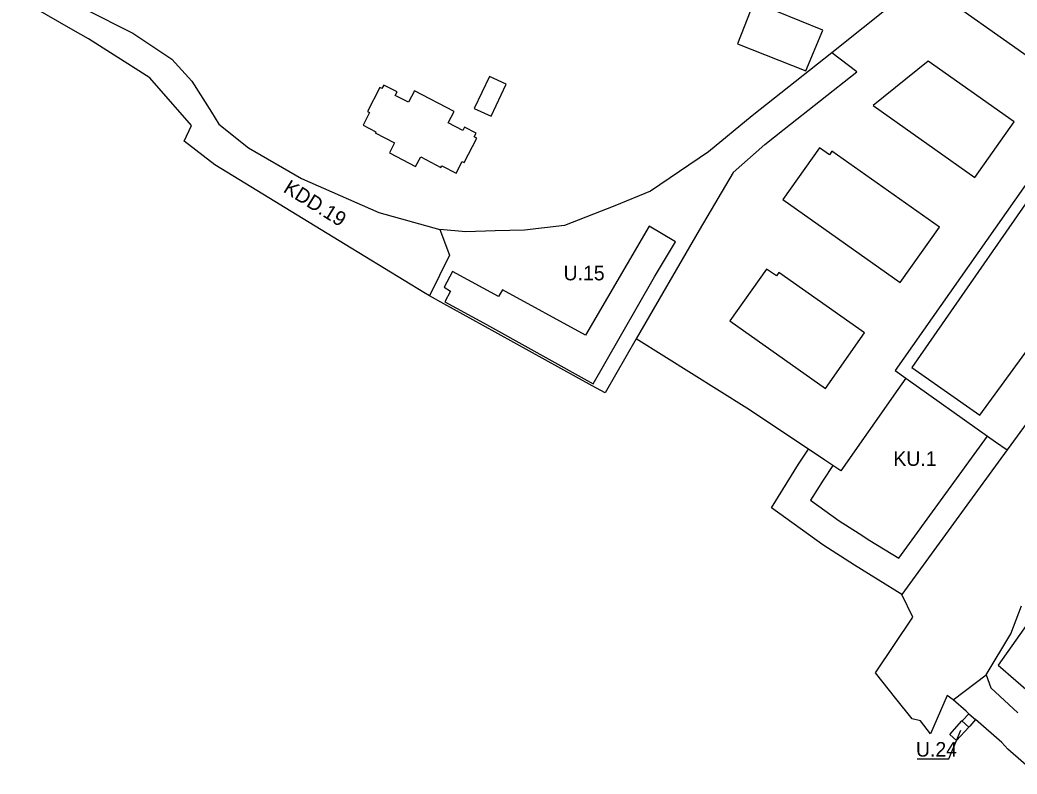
# Model space of a CAD drawing. Extents: x 7425067 to 7426806, y 5549054 to 5550619.
# Drawn here: x 7425863 to 7426205.4, y 5549368.3 to 5549627.2 of the extents above; entities that cross this region are included whole.
import ezdxf

# ---------------------------------------------------------------- set-up
doc = ezdxf.new("R2010")
doc.units = 0
for name, color, linetype in [('LIN_Linia Zabudowy Nieprzekraczalna', 7, 'Continuous'), ('LIN_linia zabudowy obowiązująca', 7, 'Continuous'), ('LIN_linie_rozgraniczajace', 7, 'Continuous'), ('TXT_Oznaczenia_przeznaczen', 7, 'Continuous')]:
    doc.layers.add(name, color=color, linetype=linetype)

msp = doc.modelspace()

# ---------------------------------------------------------------- linework, layer by layer
at = {"layer": 'LIN_Linia Zabudowy Nieprzekraczalna'}
for points in [[(7426142.1859, 5549474.236), (7426138.8249, 5549469.2092), (7426134.5528, 5549462.339), (7426144.3808, 5549455.2512), (7426151.1841, 5549450.8579), (7426154.915, 5549448.4487), (7426164.7955, 5549442.3637), (7426195.3104, 5549484.3521)], [(7426247.6304, 5549474.4023), (7426229.17, 5549448.23), (7426222.04, 5549438.34), (7426211.11, 5549422.85), (7426198.9753, 5549405.6527)], [(7426198.9753, 5549405.6527), (7426211.0357, 5549395.1516), (7426227.84, 5549380.52), (7426232.79, 5549376.21)], [(7426188.8938, 5549384.4142), (7426186.4946, 5549386.4988)]]:
    msp.add_lwpolyline(points, dxfattribs=at)
at = {"layer": 'LIN_linia zabudowy obowiązująca'}
for points in [[(7426203.81, 5549647.1), (7426184.83, 5549631.79), (7426216.68, 5549609.4), (7426230.16, 5549628.58), (7426203.81, 5549647.1)], [(7426138.73, 5549623.67), (7426115.01, 5549633.36), (7426109.38, 5549619.02), (7426132.94, 5549609.78), (7426138.73, 5549623.67)], [(7426174.96, 5549613.03), (7426155.99, 5549597.87), (7426190.91, 5549573.13), (7426204.4, 5549592.18), (7426174.96, 5549613.03)], [(7426024.24, 5549607.84), (7426019.04, 5549596.84)], [(7426019.04, 5549596.84), (7426024.79, 5549594.12), (7426029.99, 5549605.13), (7426024.24, 5549607.84)], [(7426019.69, 5549588.34), (7426015.64, 5549590.43), (7426015.06, 5549589.27), (7426010.11, 5549591.83), (7426012.18, 5549595.83), (7425998.46, 5549602.93), (7425996.4, 5549598.94), (7425991.83, 5549601.3), (7425992.52, 5549602.55), (7425988, 5549604.81), (7425987.35, 5549603.64), (7425986.64, 5549604.03), (7425982.41, 5549595.81), (7425983.11, 5549595.44), (7425980.88, 5549591.1), (7425985.23, 5549588.85), (7425985.02, 5549588.45), (7425991.63, 5549584.97), (7425989.95, 5549581.56), (7425998.87, 5549576.87), (7426000.66, 5549580.21), (7426007.61, 5549576.55), (7426007.93, 5549577.17), (7426012.86, 5549574.62), (7426014.91, 5549578.58), (7426015.6, 5549578.22), (7426019.95, 5549586.64), (7426019.06, 5549587.08), (7426019.69, 5549588.34)], [(7426178.85, 5549556.09), (7426141.87, 5549582.12), (7426141.04, 5549580.93), (7426137.58, 5549583.28), (7426125.06, 5549565.52), (7426165.35, 5549537.02), (7426178.85, 5549556.09)], [(7426221.62, 5549583.21), (7426169.3369, 5549507.8784)], [(7426192.6914, 5549491.5189), (7426246.8404, 5549565.7177)], [(7426079.08, 5549556.37), (7426057.19, 5549518.96), (7426028.73, 5549534.56), (7426027.37, 5549532.28), (7426011.56, 5549540.88)], [(7426088.13, 5549551.01), (7426079.08, 5549556.37)], [(7426059.9, 5549502.22), (7426063.91, 5549509.23), (7426080.99, 5549539.03), (7426088.13, 5549551.01)], [(7426011.56, 5549540.88), (7426008.76, 5549535.44), (7426010.87, 5549534.12), (7426008.98, 5549530.46), (7426022.25, 5549523.18), (7426059.9, 5549502.22)], [(7426106.83, 5549523.88), (7426139.63, 5549500.71), (7426153.1, 5549519.74), (7426123.63, 5549540.51), (7426122.78, 5549539.3), (7426119.34, 5549541.67), (7426106.83, 5549523.88)], [(7426169.3369, 5549507.8784), (7426192.6914, 5549491.5189)]]:
    msp.add_lwpolyline(points, dxfattribs=at)
at = {"layer": 'LIN_linie_rozgraniczajace'}
for points in [[(7425881.34, 5549623.75), (7425863.02, 5549634.35)], [(7426163.385, 5549633.14), (7426141.78, 5549615.9)], [(7425885.4, 5549630.87), (7425901.77, 5549622.65)], [(7425886.54, 5549620.75), (7425881.34, 5549623.75)], [(7425901.77, 5549622.65), (7425915.13, 5549613.7)], [(7425907.64, 5549607.3), (7425886.54, 5549620.75)], [(7426141.78, 5549615.9), (7426114.53, 5549594.24)], [(7426150.44, 5549609.41), (7426141.78, 5549615.9)], [(7425915.13, 5549613.7), (7425922.06, 5549606.19)], [(7426125.43, 5549589.71), (7426150.44, 5549609.41)], [(7425921.93, 5549591.02), (7425907.64, 5549607.3)], [(7425922.06, 5549606.19), (7425928.76, 5549595.51)], [(7425928.76, 5549595.51), (7425931.3, 5549591.46)], [(7426114.53, 5549594.24), (7426099.51, 5549581.98)], [(7425919.43, 5549585.56), (7425921.93, 5549591.02)], [(7425931.3, 5549591.46), (7425941.46, 5549583.33)], [(7426118.78, 5549584.46), (7426125.43, 5549589.71)], [(7426220.38, 5549587.66), (7426163.57, 5549506.84)], [(7425929.93, 5549577.52), (7425919.43, 5549585.56)], [(7426107.98, 5549574.78), (7426118.78, 5549584.46)], [(7425941.46, 5549583.33), (7425959.69, 5549572.75)], [(7426099.51, 5549581.98), (7426079.58, 5549568.41)], [(7425974.69, 5549550.12), (7425929.93, 5549577.52)], [(7426107.98, 5549574.78), (7426096.32, 5549555.06)], [(7425959.69, 5549572.75), (7425972.99, 5549566.91)], [(7425972.99, 5549566.91), (7425986.29, 5549561.07)], [(7426079.58, 5549568.41), (7426067.33, 5549563.43)], [(7426067.33, 5549563.43), (7426050.05, 5549556.62)], [(7425986.29, 5549561.07), (7426007.17, 5549555.26)], [(7426050.05, 5549556.62), (7426036.26, 5549555.02)], [(7426016.2, 5549554.51), (7426007.17, 5549555.26)], [(7426007.17, 5549555.26), (7426010.52, 5549546.41)], [(7426026.23, 5549554.765), (7426016.2, 5549554.51)], [(7426036.26, 5549555.02), (7426026.23, 5549554.765)], [(7426096.32, 5549555.06), (7426074.65, 5549517.69)], [(7426001.71, 5549533.58), (7425974.69, 5549550.12)], [(7426010.52, 5549546.41), (7426003.64, 5549532.52)], [(7426003.64, 5549532.52), (7426001.71, 5549533.58)], [(7426008.62, 5549529.76), (7426003.64, 5549532.52)], [(7426021.84, 5549522.45), (7426008.62, 5549529.76)], [(7426059.53, 5549501.58), (7426021.84, 5549522.45)], [(7426074.65, 5549517.69), (7426063.97, 5549499.19)], [(7426112.66, 5549493.95), (7426074.65, 5549517.69)], [(7426163.57, 5549506.84), (7426167.27, 5549504.26)], [(7426167.27, 5549504.26), (7426164.5117, 5549500.337)], [(7426167.27, 5549504.26), (7426195.3104, 5549484.3521), (7426198.054, 5549482.4042)], [(7426219.75, 5549503.84), (7426202.0428, 5549479.5722), (7426192.8, 5549466.905)], [(7426063.97, 5549499.19), (7426059.53, 5549501.58)], [(7426164.5117, 5549500.337), (7426144.89, 5549472.43)], [(7426133.87, 5549479.79), (7426112.66, 5549493.95)], [(7426198.054, 5549482.4042), (7426202.0428, 5549479.5722)], [(7426130.42, 5549474.63), (7426133.87, 5549479.79)], [(7426139.38, 5549476.11), (7426133.87, 5549479.79)], [(7426121.13, 5549459.69), (7426130.42, 5549474.63)], [(7426144.89, 5549472.43), (7426142.1859, 5549474.236), (7426139.38, 5549476.11)], [(7426192.8, 5549466.905), (7426165.85, 5549429.97)], [(7426138.74, 5549446.99), (7426121.13, 5549459.69)], [(7426149.58, 5549439.99), (7426138.74, 5549446.99)], [(7426165.85, 5549429.97), (7426149.58, 5549439.99)], [(7426169.68, 5549422.11), (7426165.85, 5549429.97)], [(7426205.15, 5549421.27), (7426206.994, 5549425.9885)], [(7426156.84, 5549402.99), (7426169.68, 5549422.11)], [(7426203.3, 5549416.44), (7426205.15, 5549421.27)], [(7426194.86, 5549402.39), (7426203.3, 5549416.44)], [(7426163.83, 5549394.2), (7426156.84, 5549402.99)], [(7426183.5, 5549393.73), (7426194.86, 5549402.39)], [(7426194.86, 5549402.39), (7426196.44, 5549397.9)], [(7426196.44, 5549397.9), (7426205.73, 5549389.26)], [(7426169.38, 5549387.2), (7426163.83, 5549394.2)], [(7426181.45, 5549395.24), (7426175.76, 5549382.08)], [(7426183.5, 5549393.73), (7426181.45, 5549395.24)], [(7426187.96, 5549389.91), (7426183.5, 5549393.73)], [(7426186.79, 5549386.81), (7426188.84, 5549388.97)], [(7426188.84, 5549388.97), (7426187.96, 5549389.91)], [(7426188.84, 5549388.97), (7426191.13, 5549387.03)], [(7426172.25, 5549386.57), (7426169.38, 5549387.2)], [(7426175.76, 5549382.08), (7426172.25, 5549386.57)], [(7426182.33, 5549381.87), (7426186.4946, 5549386.4988), (7426186.79, 5549386.81)], [(7426191.13, 5549387.03), (7426189.17, 5549384.72)], [(7426200.19, 5549379.08), (7426191.13, 5549387.03)], [(7426184.68, 5549379.75), (7426182.33, 5549381.87)], [(7426189.17, 5549384.72), (7426188.8938, 5549384.4142), (7426184.68, 5549379.75)], [(7426202.28, 5549376.85), (7426200.19, 5549379.08)], [(7426212.1, 5549368.28), (7426202.28, 5549376.85)]]:
    msp.add_lwpolyline(points, dxfattribs=at)
at = {"layer": 'TXT_Oznaczenia_przeznaczen'}
msp.add_lwpolyline([(7426171.1128, 5549373.5517), (7426182.0177, 5549373.5517), (7426186.1627, 5549383.337)], dxfattribs=at)

# ---------------------------------------------------------------- texts
msp.add_text('KDD.19', height=5, rotation=328.196222, dxfattribs=at).set_placement((7425953.1335, 5549568.3506))
for s, p in [('U.15', (7426049.6891, 5549537.8056)), ('KU.1', (7426162.944, 5549474.0923)), ('U.24', (7426170.706, 5549374.2658))]:
    msp.add_text(s, height=5, dxfattribs=at).set_placement(p)

doc.saveas('drawing.dxf')
